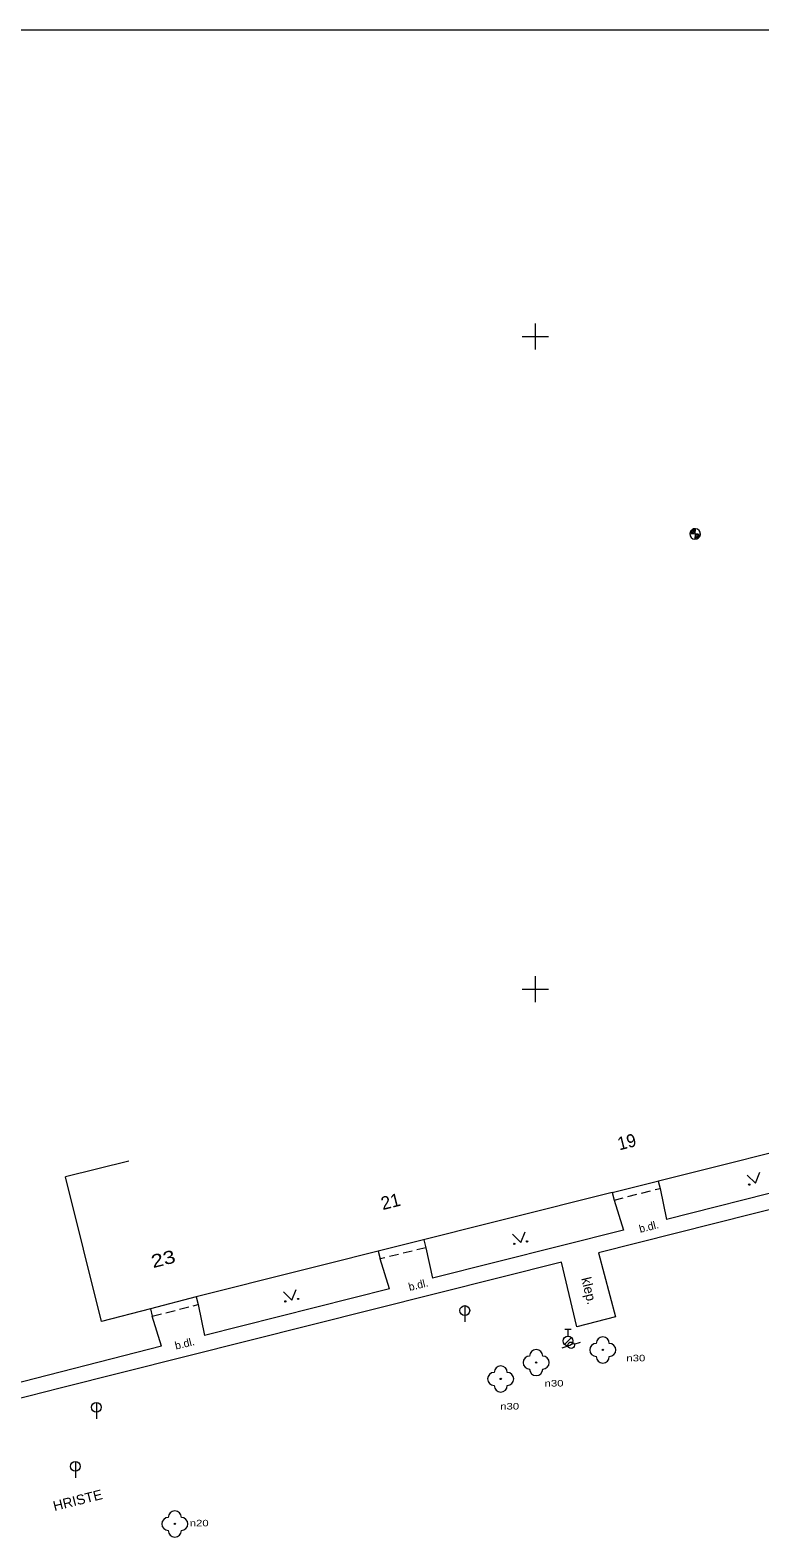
# Model space of a CAD drawing. Extents: x -670514 to -669423, y -1130798 to -1130123.
# Drawn here: x -669788.7 to -669732.8, y -1130592 to -1130476.5 of the extents above; entities that cross this region are included whole.
import ezdxf
from ezdxf.enums import TextEntityAlignment as Align

# ---------------------------------------------------------------- set-up
doc = ezdxf.new("R2010")
doc.units = 0
doc.header["$LTSCALE"] = 0.24
doc.linetypes.add('MEDIUM_DASHED', pattern=[4.5, 3, -1.5])
for name, color, linetype, lineweight in [('10', 7, 'Continuous', 13), ('22', 7, 'Continuous', 13), ('27', 7, 'Continuous', 13), ('28', 7, 'Continuous', 13), ('36', 7, 'Continuous', 13), ('38', 7, 'Continuous', 13), ('5', 7, 'Continuous', 13), ('60', 7, 'Continuous', 13), ('61', 7, 'Continuous', 13)]:
    doc.layers.add(name, color=color, linetype=linetype, lineweight=lineweight)
for name, color, linetype in [('40', 7, 'Continuous'), ('42', 7, 'Continuous'), ('44', 7, 'Continuous'), ('47', 7, 'Continuous')]:
    doc.layers.add(name, color=color, linetype=linetype)

msp = doc.modelspace()

# ---------------------------------------------------------------- linework, layer by layer
at = {"layer": '10'}
for p, q in [((-669711.698, -1130561.786), (-669745.171, -1130570.199)), ((-669725.823, -1130564.08), (-669739.953, -1130567.648)), ((-669740.451, -1130565.267), (-669739.953, -1130567.648)), ((-669758.388, -1130569.809), (-669757.882, -1130572.142)), ((-669748.005, -1130570.931), (-669786.393, -1130580.581)), ((-669761.177, -1130572.963), (-669761.893, -1130570.672)), ((-669761.177, -1130572.963), (-669775.354, -1130576.541)), ((-669775.828, -1130574.165), (-669775.354, -1130576.541)), ((-669778.633, -1130577.366), (-669779.343, -1130575.066)), ((-669778.633, -1130577.366), (-669795.958, -1130581.787)), ((-669786.393, -1130580.581), (-669842.834, -1130594.715))]:
    msp.add_line(p, q, dxfattribs=at)
for points in [[(-669743.966, -1130566.17), (-669743.259, -1130568.479), (-669757.882, -1130572.142)], [(-669745.171, -1130570.199), (-669743.871, -1130575.113), (-669746.82, -1130575.873), (-669748.005, -1130570.931)]]:
    msp.add_lwpolyline(points, dxfattribs=at)
at = {"layer": '22'}
for centre in [(-669744.834, -1130577.646), (-669749.937, -1130578.61), (-669752.654, -1130579.869), (-669777.616, -1130590.976)]:
    msp.add_circle(centre, 0.05, dxfattribs=at)
for centre, start, end in [((-669745.334, -1130577.646), 90, 270), ((-669744.834, -1130577.146), 0, 180), ((-669744.334, -1130577.646), 270, 90), ((-669750.437, -1130578.61), 90, 270), ((-669749.937, -1130578.11), 0, 180), ((-669749.437, -1130578.61), 270, 90), ((-669744.834, -1130578.146), 180, 0), ((-669753.154, -1130579.869), 90, 270), ((-669752.654, -1130579.369), 0, 180), ((-669752.154, -1130579.869), 270, 90), ((-669749.937, -1130579.11), 180, 0), ((-669752.654, -1130580.369), 180, 0), ((-669778.116, -1130590.976), 90, 270), ((-669777.616, -1130590.476), 0, 180), ((-669777.116, -1130590.976), 270, 90), ((-669777.616, -1130591.476), 180, 0)]:
    msp.add_arc(centre, 0.5, start, end, dxfattribs=at)
at = {"layer": '27'}
for p, q in [((-669755.406, -1130574.251), (-669755.406, -1130575.501)), ((-669783.628, -1130581.66), (-669783.628, -1130582.91)), ((-669785.236, -1130586.19), (-669785.236, -1130587.44))]:
    msp.add_line(p, q, dxfattribs=at)
for centre in [(-669755.4056, -1130574.6261), (-669783.6276, -1130582.0351), (-669785.2356, -1130586.5651)]:
    msp.add_circle(centre, 0.375, dxfattribs=at)
at = {"layer": '28'}
for p, q in [((-669747.749, -1130576.055), (-669747.249, -1130576.055)), ((-669747.499, -1130576.58), (-669747.499, -1130576.055)), ((-669747.764, -1130577.22), (-669747.234, -1130576.69)), ((-669747.026, -1130577.208), (-669746.551, -1130577.053)), ((-669747.502, -1130577.364), (-669747.977, -1130577.519))]:
    msp.add_line(p, q, dxfattribs=at)
for centre, radius in [((-669747.499, -1130576.955), 0.375), ((-669747.2642, -1130577.2863), 0.25)]:
    msp.add_circle(centre, radius, dxfattribs=at)
at = {"layer": '36'}
for points in [[(-669733.785, -1130564.247), (-669733.13, -1130564.867), (-669732.81, -1130564.024)], [(-669751.757, -1130568.779), (-669751.124, -1130569.421), (-669750.775, -1130568.59)], [(-669769.295, -1130573.193), (-669768.662, -1130573.835), (-669768.313, -1130573.004)]]:
    msp.add_lwpolyline(points, dxfattribs=at)
for centre in [(-669733.6174, -1130564.9785), (-669751.6153, -1130569.5158), (-669750.6334, -1130569.3269), (-669768.1714, -1130573.7409), (-669769.1533, -1130573.9298)]:
    msp.add_circle(centre, 0.05, dxfattribs=at)
at = {"layer": '38'}
for p, q in [((-669737.778, -1130515.052), (-669737.992, -1130514.807)), ((-669737.749, -1130514.916), (-669737.875, -1130514.772)), ((-669738.161, -1130515.107), (-669737.759, -1130515.134)), ((-669737.995, -1130515.108), (-669738.117, -1130514.968)), ((-669737.849, -1130515.114), (-669738.045, -1130514.89)), ((-669737.759, -1130515.134), (-669737.786, -1130515.536)), ((-669737.651, -1130515.493), (-669737.769, -1130515.358)), ((-669737.564, -1130515.455), (-669737.749, -1130515.244)), ((-669737.485, -1130515.394), (-669737.696, -1130515.152)), ((-669737.428, -1130515.307), (-669737.562, -1130515.154))]:
    msp.add_line(p, q, dxfattribs=at)
msp.add_lwpolyline([(-669737.357, -1130515.161), (-669737.759, -1130515.134), (-669737.732, -1130514.732)], dxfattribs=at)
for start, end in [(86.16496, 176.16496), (356.16496, 86.16496), (176.16496, 266.16496), (266.16496, 356.16496)]:
    msp.add_arc((-669737.759, -1130515.134), 0.4031, start, end, dxfattribs=at)
at = {"layer": '5'}
for p, q in [((-669744.115, -1130565.589), (-669712.41, -1130557.622)), ((-669781.15, -1130563.174), (-669786, -1130564.388)), ((-669783.226, -1130575.471), (-669786, -1130564.388)), ((-669744.115, -1130565.589), (-669775.975, -1130573.583)), ((-669744.115, -1130565.589), (-669743.966, -1130566.17)), ((-669740.593, -1130564.704), (-669740.451, -1130565.267)), ((-669762.04, -1130570.087), (-669761.893, -1130570.672)), ((-669758.54, -1130569.208), (-669758.388, -1130569.809)), ((-669775.975, -1130573.583), (-669775.828, -1130574.165)), ((-669779.49, -1130574.484), (-669779.343, -1130575.066))]:
    msp.add_line(p, q, dxfattribs=at)
at = {"layer": '5', "linetype": 'MEDIUM_DASHED'}
for p, q in [((-669743.966, -1130566.17), (-669740.451, -1130565.267)), ((-669758.388, -1130569.809), (-669761.893, -1130570.672)), ((-669779.343, -1130575.066), (-669775.828, -1130574.165))]:
    msp.add_line(p, q, dxfattribs=at)
at = {"layer": '5'}
msp.add_lwpolyline([(-669775.975, -1130573.583), (-669779.49, -1130574.484), (-669783.226, -1130575.471)], dxfattribs=at)
at = {"layer": '60'}
msp.add_lwpolyline([(-669833.172, -1130763.536), (-669423.172, -1130763.536), (-669423.172, -1130476.536), (-669833.172, -1130476.536)], close=True, dxfattribs=at)
at = {"layer": '61'}
for p, q in [((-669750, -1130501), (-669750, -1130499)), ((-669751, -1130500), (-669749, -1130500)), ((-669750, -1130551), (-669750, -1130549)), ((-669751, -1130550), (-669749, -1130550))]:
    msp.add_line(p, q, dxfattribs=at)

# ---------------------------------------------------------------- texts
at = {"layer": '40'}
for rotation, p in [(14.108, (-669741.2371, -1130568.4886)), (14.111, (-669758.8981, -1130572.9476)), (14.111, (-669776.7931, -1130577.4466))]:
    msp.add_text('b.dl.', height=0.6, rotation=rotation, dxfattribs=at).set_placement(p, align=Align.CENTER)
at = {"layer": '42'}
msp.add_text('klep.', height=0.75, rotation=283.484, dxfattribs=at).set_placement((-669746.2451, -1130573.1966), align=Align.CENTER)
at = {"layer": '42', "width": 1.05}
msp.add_text('HRISTE', height=0.75, rotation=14.059, dxfattribs=at).set_placement((-669784.9661, -1130589.5197), align=Align.CENTER)
at = {"layer": '44'}
for s, rotation, width, p in [('19', 14.106, 0.95, (-669742.8794, -1130562.1854)), ('23', 14.18, 1.25, (-669778.387, -1130571.1535))]:
    msp.add_text(s, height=1, rotation=rotation, dxfattribs=dict(at, width=width)).set_placement(p, align=Align.CENTER)
msp.add_text('21', height=1, rotation=14.18, dxfattribs=at).set_placement((-669760.968, -1130566.7526), align=Align.CENTER)
at = {"layer": '47', "width": 1.3}
for s, p in [('n30', (-669742.3035, -1130578.516)), ('n30', (-669748.5685, -1130580.446)), ('n30', (-669751.9695, -1130582.209)), ('n20', (-669775.7525, -1130591.159))]:
    msp.add_text(s, height=0.5, dxfattribs=at).set_placement(p, align=Align.CENTER)

doc.saveas('drawing.dxf')
